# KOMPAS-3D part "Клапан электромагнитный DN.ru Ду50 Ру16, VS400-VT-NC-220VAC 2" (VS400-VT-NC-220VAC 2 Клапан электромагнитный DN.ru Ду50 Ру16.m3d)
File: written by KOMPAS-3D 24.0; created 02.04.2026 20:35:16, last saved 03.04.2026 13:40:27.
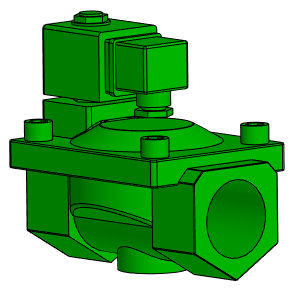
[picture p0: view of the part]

Document properties: Автор: artio; Полное имя файла: C:\Users\artio\OneDrive\Рабочий стол\Клапан электромагнитный DN.ru\VS400-VT-NC\VS400-VT-NC-220VAC 2 Клапан электромагнитный DN.ru Ду50 Ру16.m3d

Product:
- Body: Тело 1  | qty 1
    Масса: 7.119215
- Part/product: Клапан электромагнитный DN.ru Ду50 Ру16  | designation VS400-VT-NC-220VAC 2
    Масса: 3.509
    Раздел спецификации: Прочие изделия
    Примечание: D130-04703
    additional columns: ef56311e-7521-43dc-8291-0e6108b3d81d; VS400-ET-NC-220VAC 2; artio; c; Шероховатость не задана; Да

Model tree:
1. Операция без истории:1

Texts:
  VS400-VT-NC-220VAC 2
